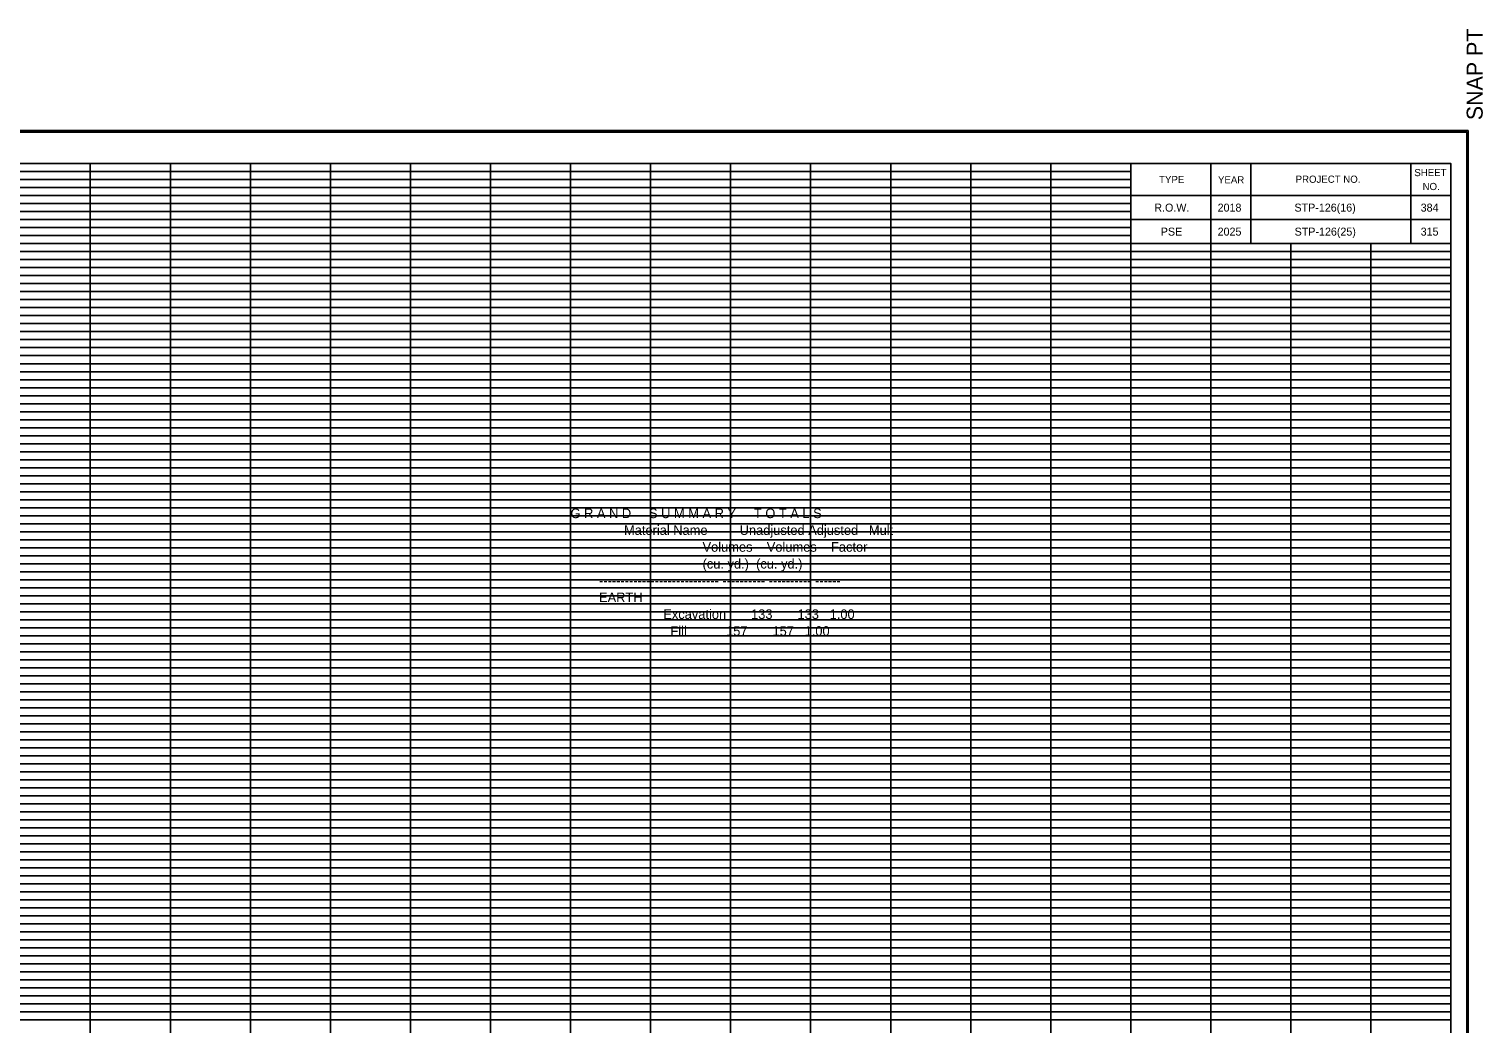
# Model space of a CAD drawing. Extents: x 980 to 1324, y 978 to 1497.
# Drawn here: x 1142.3 to 1324, y 1372.5 to 1496.8 of the extents above; entities that cross this region are included whole.
import ezdxf

# ---------------------------------------------------------------- set-up
doc = ezdxf.new("R2010")
doc.units = 0
for name, color, linetype in [('DESIGN - SCRATCH - User 1', 7, 'Continuous'), ('DESIGN - SHEET - Corner Text', 7, 'Continuous'), ('DESIGN - SHEET - Light Grid', 7, 'Continuous'), ('DESIGN - SHEET - Linework', 7, 'Continuous'), ('DESIGN - SHEET - Plot Shape', 7, 'Continuous'), ('DESIGN - TYPICAL - Text', 7, 'Continuous')]:
    doc.layers.add(name, color=color, linetype=linetype)

# ---------------------------------------------------------------- blocks, each defined once
blk = doc.blocks.new('XSTSHT')
at = {"layer": 'DESIGN - SCRATCH - User 1'}
for p, q in [((28.5, 20.45), (28.5, 20.45)), ((29.24, 20.45), (29.24, 20.45)), ((30.49, 20.45), (30.49, 20.45)), ((31.74, 20.45), (31.74, 20.45)), ((28.5, 20.15), (28.5, 20.15)), ((29.24, 20.15), (29.24, 20.15)), ((30.49, 20.15), (30.49, 20.15)), ((31.74, 20.15), (31.74, 20.15))]:
    blk.add_line(p, q, dxfattribs=at)
at = {"layer": 'DESIGN - SHEET - Light Grid'}
for p, q in [((8, 20.9), (16, 20.9)), ((16, 20.9), (24, 20.9)), ((24, 20.9), (28, 20.9)), ((8, 20.8), (16, 20.8)), ((16, 20.8), (24, 20.8)), ((24, 20.8), (28, 20.8)), ((8, 20.7), (16, 20.7)), ((8, 20.6), (16, 20.6)), ((16, 20.7), (24, 20.7)), ((16, 20.6), (24, 20.6)), ((24, 20.7), (28, 20.7)), ((24, 20.6), (28, 20.6)), ((8, 20.5), (16, 20.5)), ((8, 20.4), (16, 20.4)), ((16, 20.5), (24, 20.5)), ((16, 20.4), (24, 20.4)), ((24, 20.5), (28, 20.5)), ((24, 20.4), (28, 20.4)), ((8, 20.3), (16, 20.3)), ((8, 20.2), (16, 20.2)), ((16, 20.3), (24, 20.3)), ((16, 20.2), (24, 20.2)), ((24, 20.3), (28, 20.3)), ((24, 20.2), (28, 20.2)), ((8, 20.1), (16, 20.1)), ((16, 20.1), (24, 20.1)), ((24, 20.1), (28, 20.1)), ((8, 19.9), (16, 19.9)), ((8, 19.8), (16, 19.8)), ((16, 19.9), (24, 19.9)), ((16, 19.8), (24, 19.8)), ((24, 19.9), (32, 19.9)), ((24, 19.8), (32, 19.8)), ((8, 19.7), (16, 19.7)), ((16, 19.7), (24, 19.7)), ((24, 19.7), (32, 19.7)), ((8, 19.6), (16, 19.6)), ((8, 19.5), (16, 19.5)), ((16, 19.6), (24, 19.6)), ((16, 19.5), (24, 19.5)), ((24, 19.6), (32, 19.6)), ((24, 19.5), (32, 19.5)), ((8, 19.4), (16, 19.4)), ((8, 19.3), (16, 19.3)), ((16, 19.4), (24, 19.4)), ((16, 19.3), (24, 19.3)), ((24, 19.4), (32, 19.4)), ((24, 19.3), (32, 19.3)), ((8, 19.2), (16, 19.2)), ((8, 19.1), (16, 19.1)), ((16, 19.2), (24, 19.2)), ((16, 19.1), (24, 19.1)), ((24, 19.2), (32, 19.2)), ((24, 19.1), (32, 19.1)), ((8, 18.9), (16, 18.9)), ((16, 18.9), (24, 18.9)), ((24, 18.9), (32, 18.9)), ((8, 18.8), (16, 18.8)), ((16, 18.8), (24, 18.8)), ((24, 18.8), (32, 18.8)), ((8, 18.7), (16, 18.7)), ((8, 18.6), (16, 18.6)), ((16, 18.7), (24, 18.7)), ((16, 18.6), (24, 18.6)), ((24, 18.7), (32, 18.7)), ((24, 18.6), (32, 18.6)), ((8, 18.5), (16, 18.5)), ((8, 18.4), (16, 18.4)), ((16, 18.5), (24, 18.5)), ((16, 18.4), (24, 18.4)), ((24, 18.5), (32, 18.5)), ((24, 18.4), (32, 18.4)), ((8, 18.3), (16, 18.3)), ((8, 18.2), (16, 18.2)), ((16, 18.3), (24, 18.3)), ((16, 18.2), (24, 18.2)), ((24, 18.3), (32, 18.3)), ((24, 18.2), (32, 18.2)), ((8, 18.1), (16, 18.1)), ((16, 18.1), (24, 18.1)), ((24, 18.1), (32, 18.1)), ((8, 17.9), (16, 17.9)), ((16, 17.9), (24, 17.9)), ((24, 17.9), (32, 17.9)), ((8, 17.8), (16, 17.8)), ((8, 17.7), (16, 17.7)), ((16, 17.8), (24, 17.8)), ((16, 17.7), (24, 17.7)), ((24, 17.8), (32, 17.8)), ((24, 17.7), (32, 17.7)), ((8, 17.6), (16, 17.6)), ((8, 17.5), (16, 17.5)), ((16, 17.6), (24, 17.6)), ((16, 17.5), (24, 17.5)), ((24, 17.6), (32, 17.6)), ((24, 17.5), (32, 17.5)), ((8, 17.4), (16, 17.4)), ((8, 17.3), (16, 17.3)), ((16, 17.4), (24, 17.4)), ((16, 17.3), (24, 17.3)), ((24, 17.4), (32, 17.4)), ((24, 17.3), (32, 17.3)), ((8, 17.2), (16, 17.2)), ((8, 17.1), (16, 17.1)), ((16, 17.2), (24, 17.2)), ((16, 17.1), (24, 17.1)), ((24, 17.2), (32, 17.2)), ((24, 17.1), (32, 17.1)), ((8, 16.9), (16, 16.9)), ((16, 16.9), (24, 16.9)), ((24, 16.9), (32, 16.9)), ((8, 16.8), (16, 16.8)), ((16, 16.8), (24, 16.8)), ((24, 16.8), (32, 16.8)), ((8, 16.7), (16, 16.7)), ((8, 16.6), (16, 16.6)), ((16, 16.7), (24, 16.7)), ((16, 16.6), (24, 16.6)), ((24, 16.7), (32, 16.7)), ((24, 16.6), (32, 16.6)), ((8, 16.5), (16, 16.5)), ((8, 16.4), (16, 16.4)), ((16, 16.5), (24, 16.5)), ((16, 16.4), (24, 16.4)), ((24, 16.5), (32, 16.5)), ((24, 16.4), (32, 16.4)), ((8, 16.3), (16, 16.3)), ((8, 16.2), (16, 16.2)), ((16, 16.3), (24, 16.3)), ((16, 16.2), (24, 16.2)), ((24, 16.3), (32, 16.3)), ((24, 16.2), (32, 16.2)), ((8, 16.1), (16, 16.1)), ((16, 16.1), (24, 16.1)), ((24, 16.1), (32, 16.1)), ((8, 15.9), (16, 15.9)), ((16, 15.9), (24, 15.9)), ((24, 15.9), (32, 15.9)), ((8, 15.8), (16, 15.8)), ((8, 15.7), (16, 15.7)), ((16, 15.8), (24, 15.8)), ((16, 15.7), (24, 15.7)), ((24, 15.8), (32, 15.8)), ((24, 15.7), (32, 15.7)), ((8, 15.6), (16, 15.6)), ((8, 15.5), (16, 15.5)), ((16, 15.6), (24, 15.6)), ((16, 15.5), (24, 15.5)), ((24, 15.6), (32, 15.6)), ((24, 15.5), (32, 15.5)), ((8, 15.4), (16, 15.4)), ((8, 15.3), (16, 15.3)), ((16, 15.4), (24, 15.4)), ((16, 15.3), (24, 15.3)), ((24, 15.4), (32, 15.4)), ((24, 15.3), (32, 15.3)), ((8, 15.2), (16, 15.2)), ((8, 15.1), (16, 15.1)), ((16, 15.2), (24, 15.2)), ((16, 15.1), (24, 15.1)), ((24, 15.2), (32, 15.2)), ((24, 15.1), (32, 15.1)), ((8, 14.9), (16, 14.9)), ((16, 14.9), (24, 14.9)), ((24, 14.9), (32, 14.9)), ((8, 14.8), (16, 14.8)), ((16, 14.8), (24, 14.8)), ((24, 14.8), (32, 14.8)), ((8, 14.7), (16, 14.7)), ((8, 14.6), (16, 14.6)), ((16, 14.7), (24, 14.7)), ((16, 14.6), (24, 14.6)), ((24, 14.7), (32, 14.7)), ((24, 14.6), (32, 14.6)), ((8, 14.5), (16, 14.5)), ((8, 14.4), (16, 14.4)), ((16, 14.5), (24, 14.5)), ((16, 14.4), (24, 14.4)), ((24, 14.5), (32, 14.5)), ((24, 14.4), (32, 14.4)), ((8, 14.3), (16, 14.3)), ((8, 14.2), (16, 14.2)), ((16, 14.3), (24, 14.3)), ((16, 14.2), (24, 14.2)), ((24, 14.3), (32, 14.3)), ((24, 14.2), (32, 14.2)), ((8, 14.1), (16, 14.1)), ((16, 14.1), (24, 14.1)), ((24, 14.1), (32, 14.1)), ((8, 13.9), (16, 13.9)), ((16, 13.9), (24, 13.9)), ((24, 13.9), (32, 13.9)), ((8, 13.8), (16, 13.8)), ((8, 13.7), (16, 13.7)), ((16, 13.8), (24, 13.8)), ((16, 13.7), (24, 13.7)), ((24, 13.8), (32, 13.8)), ((24, 13.7), (32, 13.7)), ((8, 13.6), (16, 13.6)), ((8, 13.5), (16, 13.5)), ((16, 13.6), (24, 13.6)), ((16, 13.5), (24, 13.5)), ((24, 13.6), (32, 13.6)), ((24, 13.5), (32, 13.5)), ((8, 13.4), (16, 13.4)), ((8, 13.3), (16, 13.3)), ((16, 13.4), (24, 13.4)), ((16, 13.3), (24, 13.3)), ((24, 13.4), (32, 13.4)), ((24, 13.3), (32, 13.3)), ((8, 13.2), (16, 13.2)), ((8, 13.1), (16, 13.1)), ((16, 13.2), (24, 13.2)), ((16, 13.1), (24, 13.1)), ((24, 13.2), (32, 13.2)), ((24, 13.1), (32, 13.1)), ((8, 12.9), (16, 12.9)), ((16, 12.9), (24, 12.9)), ((24, 12.9), (32, 12.9)), ((8, 12.8), (16, 12.8)), ((16, 12.8), (24, 12.8)), ((24, 12.8), (32, 12.8)), ((8, 12.7), (16, 12.7)), ((8, 12.6), (16, 12.6)), ((16, 12.7), (24, 12.7)), ((16, 12.6), (24, 12.6)), ((24, 12.7), (32, 12.7)), ((24, 12.6), (32, 12.6)), ((8, 12.5), (16, 12.5)), ((8, 12.4), (16, 12.4)), ((16, 12.5), (24, 12.5)), ((16, 12.4), (24, 12.4)), ((24, 12.5), (32, 12.5)), ((24, 12.4), (32, 12.4)), ((8, 12.3), (16, 12.3)), ((8, 12.2), (16, 12.2)), ((16, 12.3), (24, 12.3)), ((16, 12.2), (24, 12.2)), ((24, 12.3), (32, 12.3)), ((24, 12.2), (32, 12.2)), ((8, 12.1), (16, 12.1)), ((16, 12.1), (24, 12.1)), ((24, 12.1), (32, 12.1)), ((8, 11.9), (16, 11.9)), ((16, 11.9), (24, 11.9)), ((24, 11.9), (32, 11.9)), ((8, 11.8), (16, 11.8)), ((8, 11.7), (16, 11.7)), ((16, 11.8), (24, 11.8)), ((16, 11.7), (24, 11.7)), ((24, 11.8), (32, 11.8)), ((24, 11.7), (32, 11.7)), ((8, 11.6), (16, 11.6)), ((8, 11.5), (16, 11.5)), ((16, 11.6), (24, 11.6)), ((16, 11.5), (24, 11.5)), ((24, 11.6), (32, 11.6)), ((24, 11.5), (32, 11.5)), ((8, 11.4), (16, 11.4)), ((8, 11.3), (16, 11.3)), ((16, 11.4), (24, 11.4)), ((16, 11.3), (24, 11.3)), ((24, 11.4), (32, 11.4)), ((24, 11.3), (32, 11.3)), ((8, 11.2), (16, 11.2)), ((8, 11.1), (16, 11.1)), ((16, 11.2), (24, 11.2)), ((16, 11.1), (24, 11.1)), ((24, 11.2), (32, 11.2)), ((24, 11.1), (32, 11.1)), ((8, 10.9), (16, 10.9)), ((16, 10.9), (24, 10.9)), ((24, 10.9), (32, 10.9)), ((8, 10.8), (16, 10.8)), ((16, 10.8), (24, 10.8)), ((24, 10.8), (32, 10.8)), ((8, 10.7), (16, 10.7)), ((8, 10.6), (16, 10.6)), ((16, 10.7), (24, 10.7)), ((16, 10.6), (24, 10.6)), ((24, 10.7), (32, 10.7)), ((24, 10.6), (32, 10.6)), ((8, 10.5), (16, 10.5)), ((8, 10.4), (16, 10.4)), ((16, 10.5), (24, 10.5)), ((16, 10.4), (24, 10.4)), ((24, 10.5), (32, 10.5)), ((24, 10.4), (32, 10.4)), ((8, 10.3), (16, 10.3)), ((16, 10.3), (24, 10.3)), ((24, 10.3), (32, 10.3))]:
    blk.add_line(p, q, dxfattribs=at)
at = {"layer": 'DESIGN - SHEET - Linework'}
for p, q in [((-1.823, 21.414), (32.217, 21.414)), ((32.217, 21.414), (32.217, -0.414)), ((15, 0), (15, 21)), ((16, 0), (16, 21)), ((17, 0), (17, 21)), ((18, 0), (18, 21)), ((19, 0), (19, 21)), ((20, 0), (20, 21)), ((21, 0), (21, 21)), ((22, 0), (22, 21)), ((23, 0), (23, 21)), ((24, 0), (24, 21)), ((25, 0), (25, 21)), ((26, 0), (26, 21)), ((27, 0), (27, 21)), ((0, 20), (28, 20)), ((28, 0), (28, 20)), ((29, 0), (29, 20)), ((30, 0), (30, 20)), ((31, 0), (31, 20)), ((0, 19), (32, 19)), ((0, 18), (32, 18)), ((0, 17), (32, 17)), ((0, 16), (32, 16)), ((0, 15), (32, 15)), ((0, 14), (32, 14)), ((0, 13), (32, 13)), ((0, 12), (32, 12)), ((0, 11), (32, 11))]:
    blk.add_line(p, q, dxfattribs=at)
for points in [[(0, 21), (0, 0), (32, 0), (32, 21), (0, 21)], [(28, 21), (28, 20), (32, 20), (32, 21), (31.5, 21), (31.5, 20), (29.5, 20), (29.5, 21), (29, 21), (29, 20), (32, 20), (28, 20), (28, 20.3), (32, 20.3), (32, 20.6), (28, 20.6)]]:
    blk.add_lwpolyline(points, dxfattribs=at)
at = {"layer": 'DESIGN - SHEET - Plot Shape'}
for points in [[(-1.803, 21.394), (32.197, 21.394), (32.197, -0.394), (-1.803, -0.394)], [(-0.85, 21), (32, 21), (32, -0.25), (-0.85, -0.25)]]:
    blk.add_lwpolyline(points, close=True, dxfattribs=at)
at = {"layer": 'DESIGN - SHEET - Corner Text'}
blk.add_text('  SNAP PT', height=0.2, rotation=90, dxfattribs=at).set_placement((32.397, 21.394))
for s, p in [('SHEET', (31.543, 20.843)), ('TYPE', (28.354, 20.756)), ('YEAR', (29.09, 20.752)), ('PROJECT NO.', (30.06, 20.76)), ('NO.', (31.646, 20.669))]:
    blk.add_text(s, height=0.09, dxfattribs=at).set_placement(p)

msp = doc.modelspace()

# ---------------------------------------------------------------- linework, layer by layer
at = {"layer": 'DESIGN - SHEET - Plot Shape'}
msp.add_lwpolyline([(991.5, 1267.5), (1320, 1267.5), (1320, 1480), (991.5, 1480)], close=True, dxfattribs=at)

# ---------------------------------------------------------------- block references
at = {"layer": 'DESIGN - TYPICAL - Text', "xscale": 10, "yscale": 10}
msp.add_blockref('XSTSHT', (1000, 1270), dxfattribs=at)

# ---------------------------------------------------------------- texts
at = {"layer": 'DESIGN - SHEET - Corner Text'}
for s, p in [('R.O.W.', (1282.94, 1474)), ('2018', (1290.85, 1474)), ('STP-126(16)', (1300.45, 1474)), ('384', (1316.22, 1474)), ('PSE', (1283.75, 1471)), ('2025', (1290.85, 1471)), ('STP-126(25)', (1300.47, 1471)), ('315', (1316.22, 1471))]:
    msp.add_text(s, height=1, dxfattribs=at).set_placement(p)
at = {"layer": 'DESIGN - TYPICAL - Text'}
for s, p in [('G R A N D     S U M M A R Y     T O T A L S', (1210, 1435.7)), ('               Material Name         Unadjusted Adjusted   Mult', (1210, 1433.6)), ('                                     Volumes    Volumes    Factor', (1210, 1431.5)), ('                                     (cu. yd.)  (cu. yd.)', (1210, 1429.4)), ('        ---------------------------- ---------- ---------- ------', (1210, 1427.3)), ('        EARTH', (1210, 1425.2)), ('                          Excavation       133       133   1.00', (1210, 1423.1)), ('                            Fill           157       157   1.00', (1210, 1421))]:
    msp.add_text(s, height=1.2, dxfattribs=at).set_placement(p)

doc.saveas('drawing.dxf')
